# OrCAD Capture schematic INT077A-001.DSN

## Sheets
1 P1_8044: size C; title: TUSB8044RGCEVM INT077-001; rev: A.0; company: Texas Instruments, CIS/ICP; note: GAGGIA.DSN
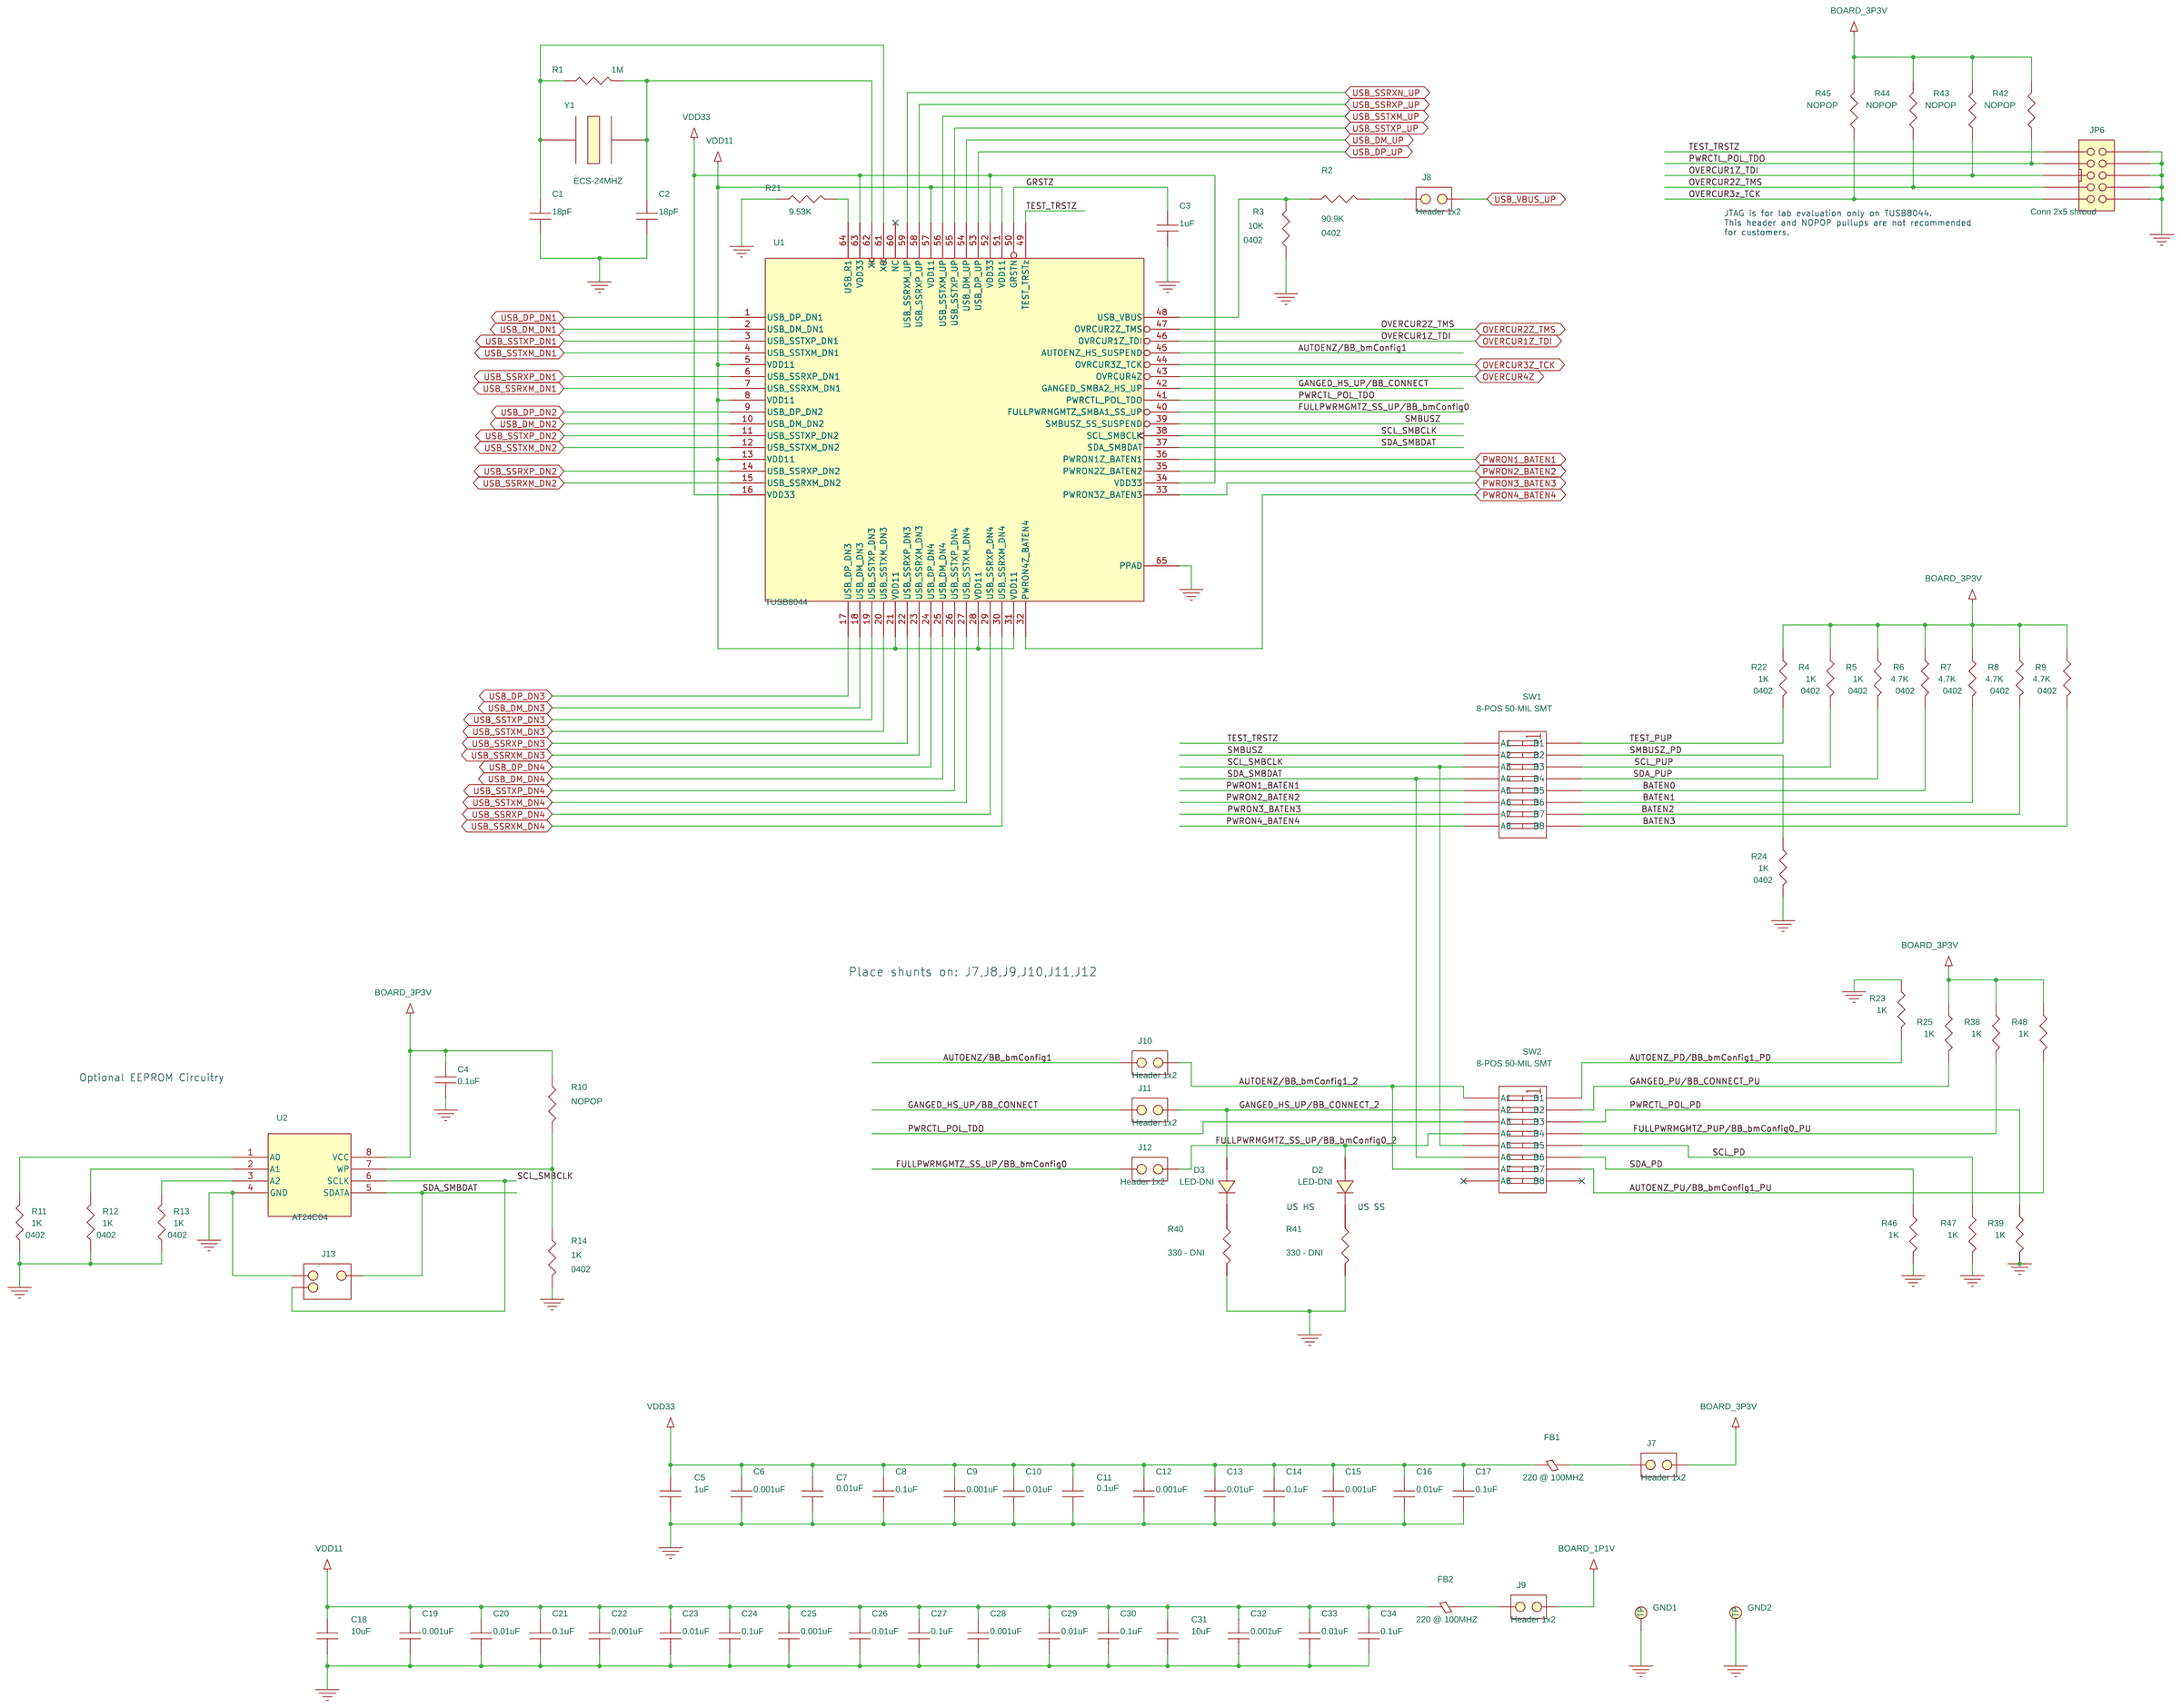
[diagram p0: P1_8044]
2 P2_CONNECTORS: size C; title: TUSB8044RGCEVM INT077-001: USB3 CONNECTORS
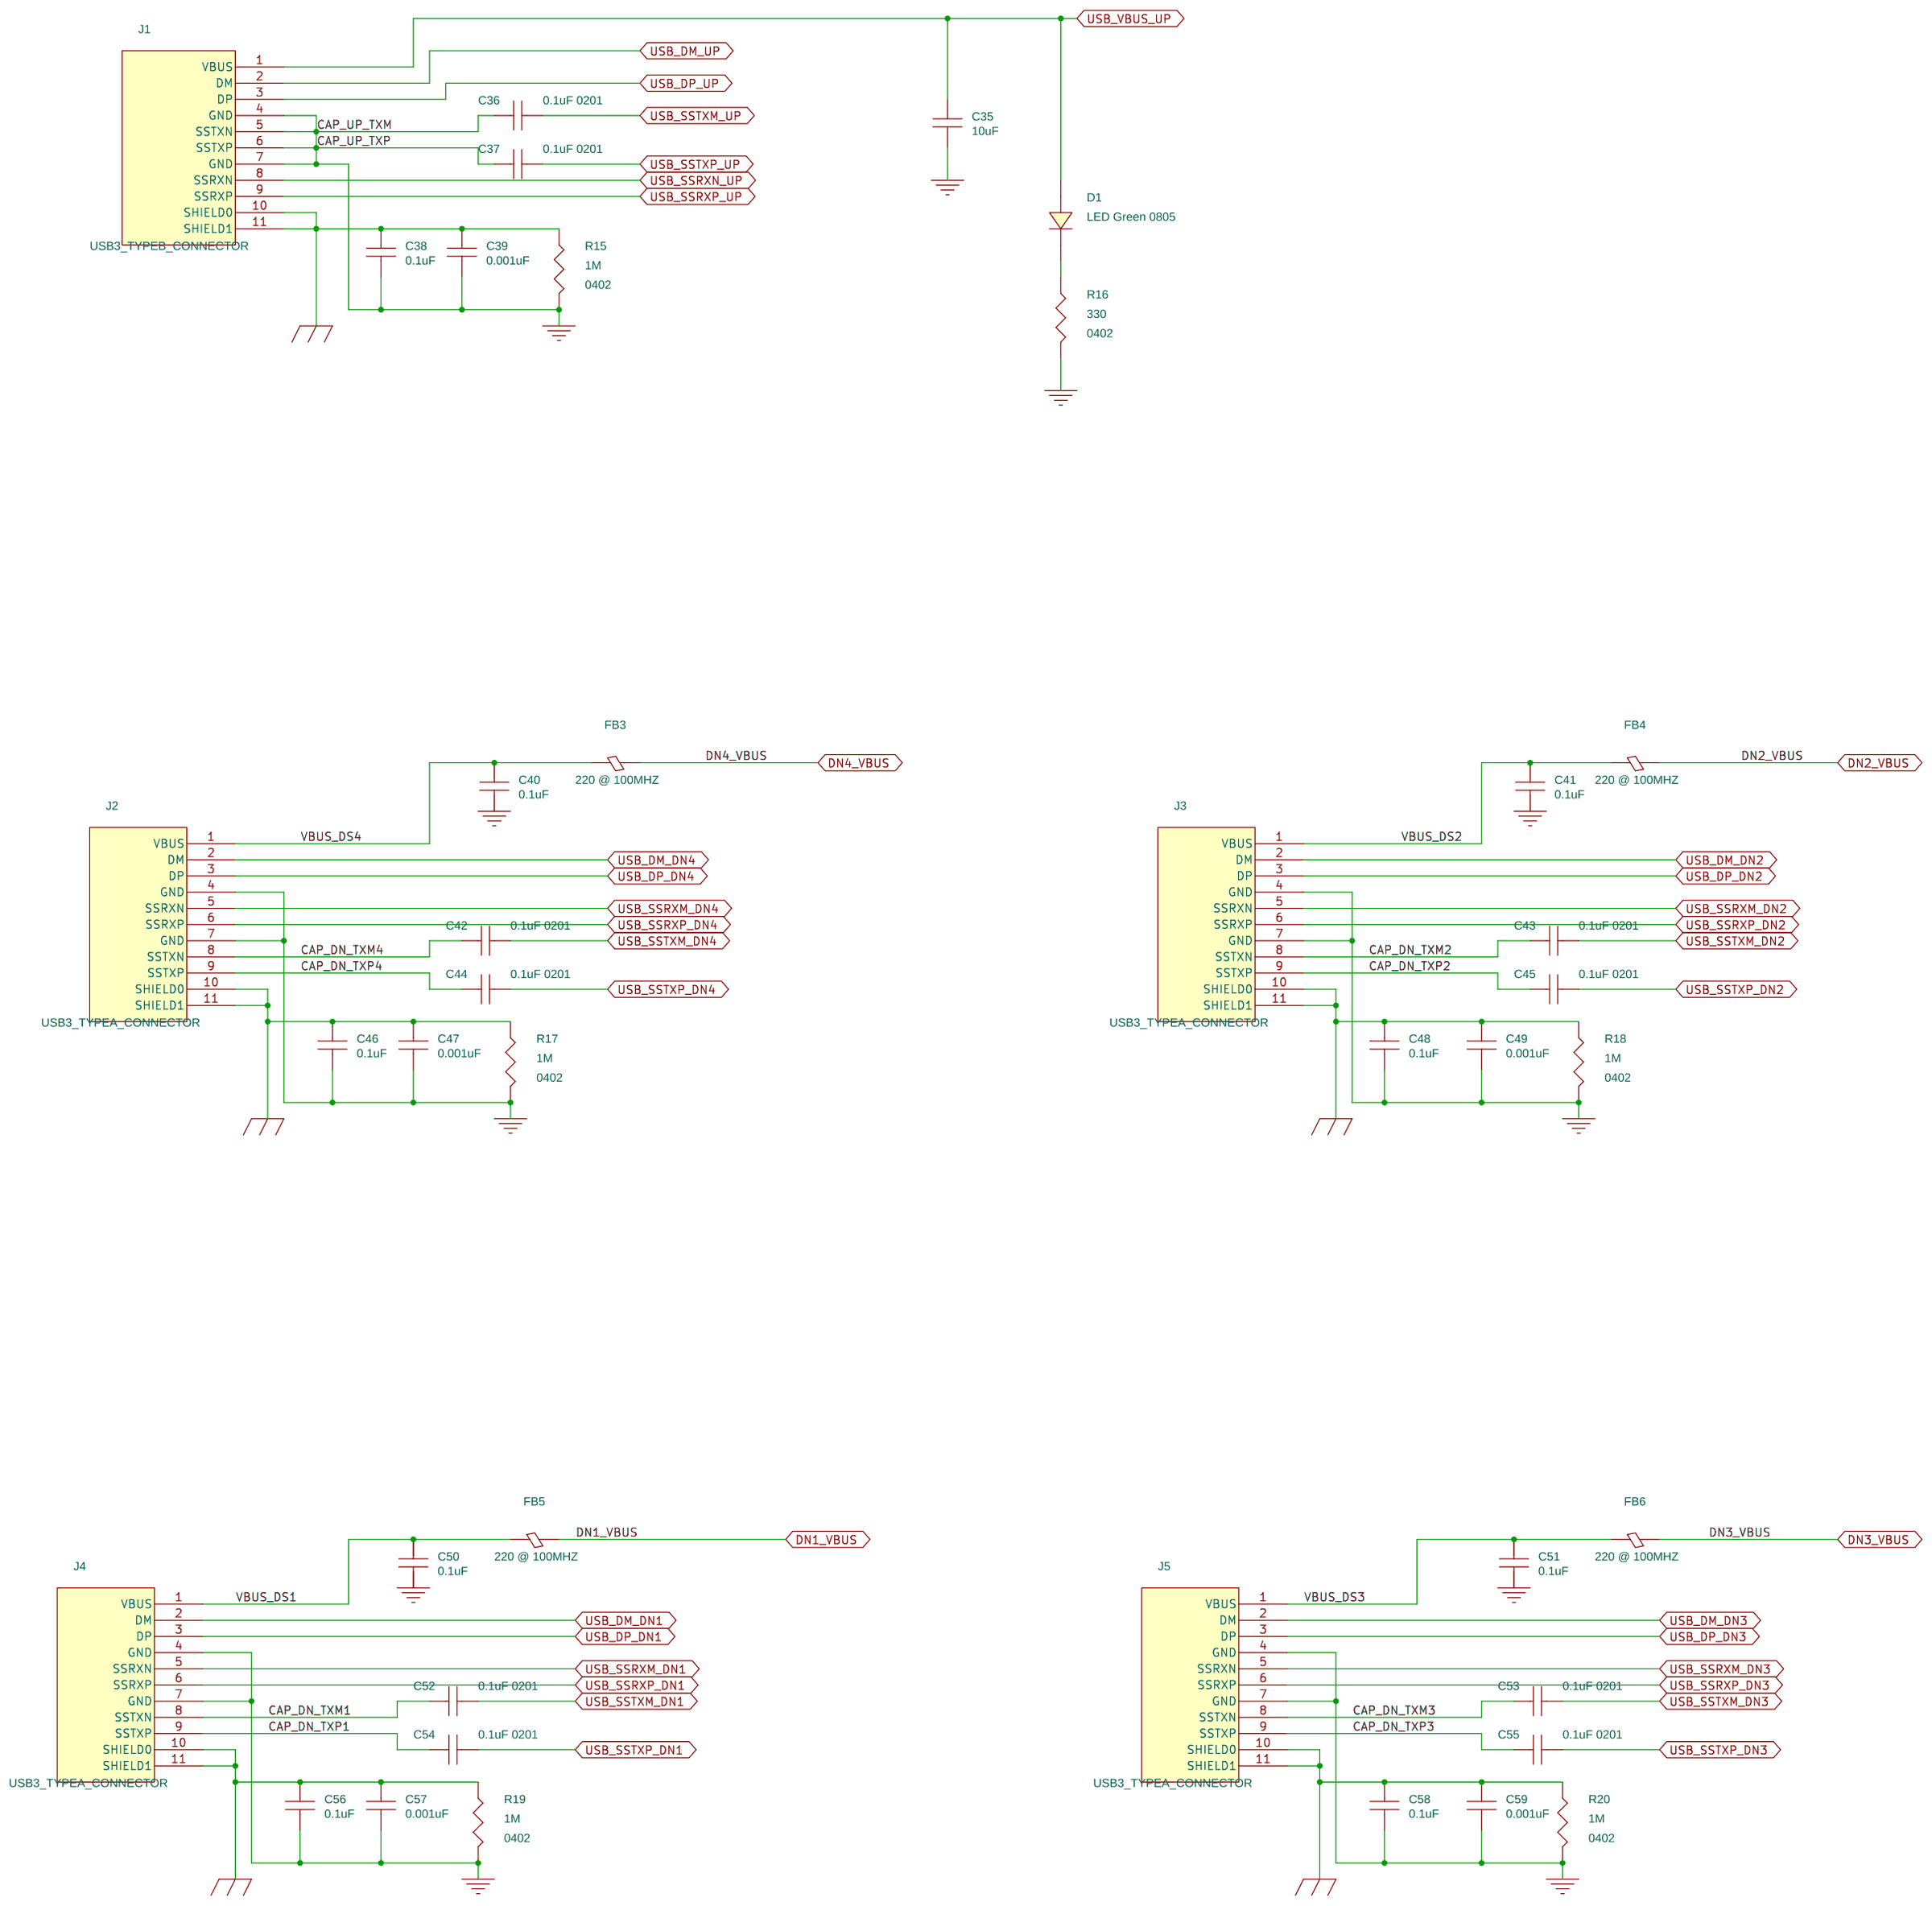
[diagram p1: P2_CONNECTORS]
3 P3_POWER: size C; title: TUSB8044RGCEVM INT077-001: POWER
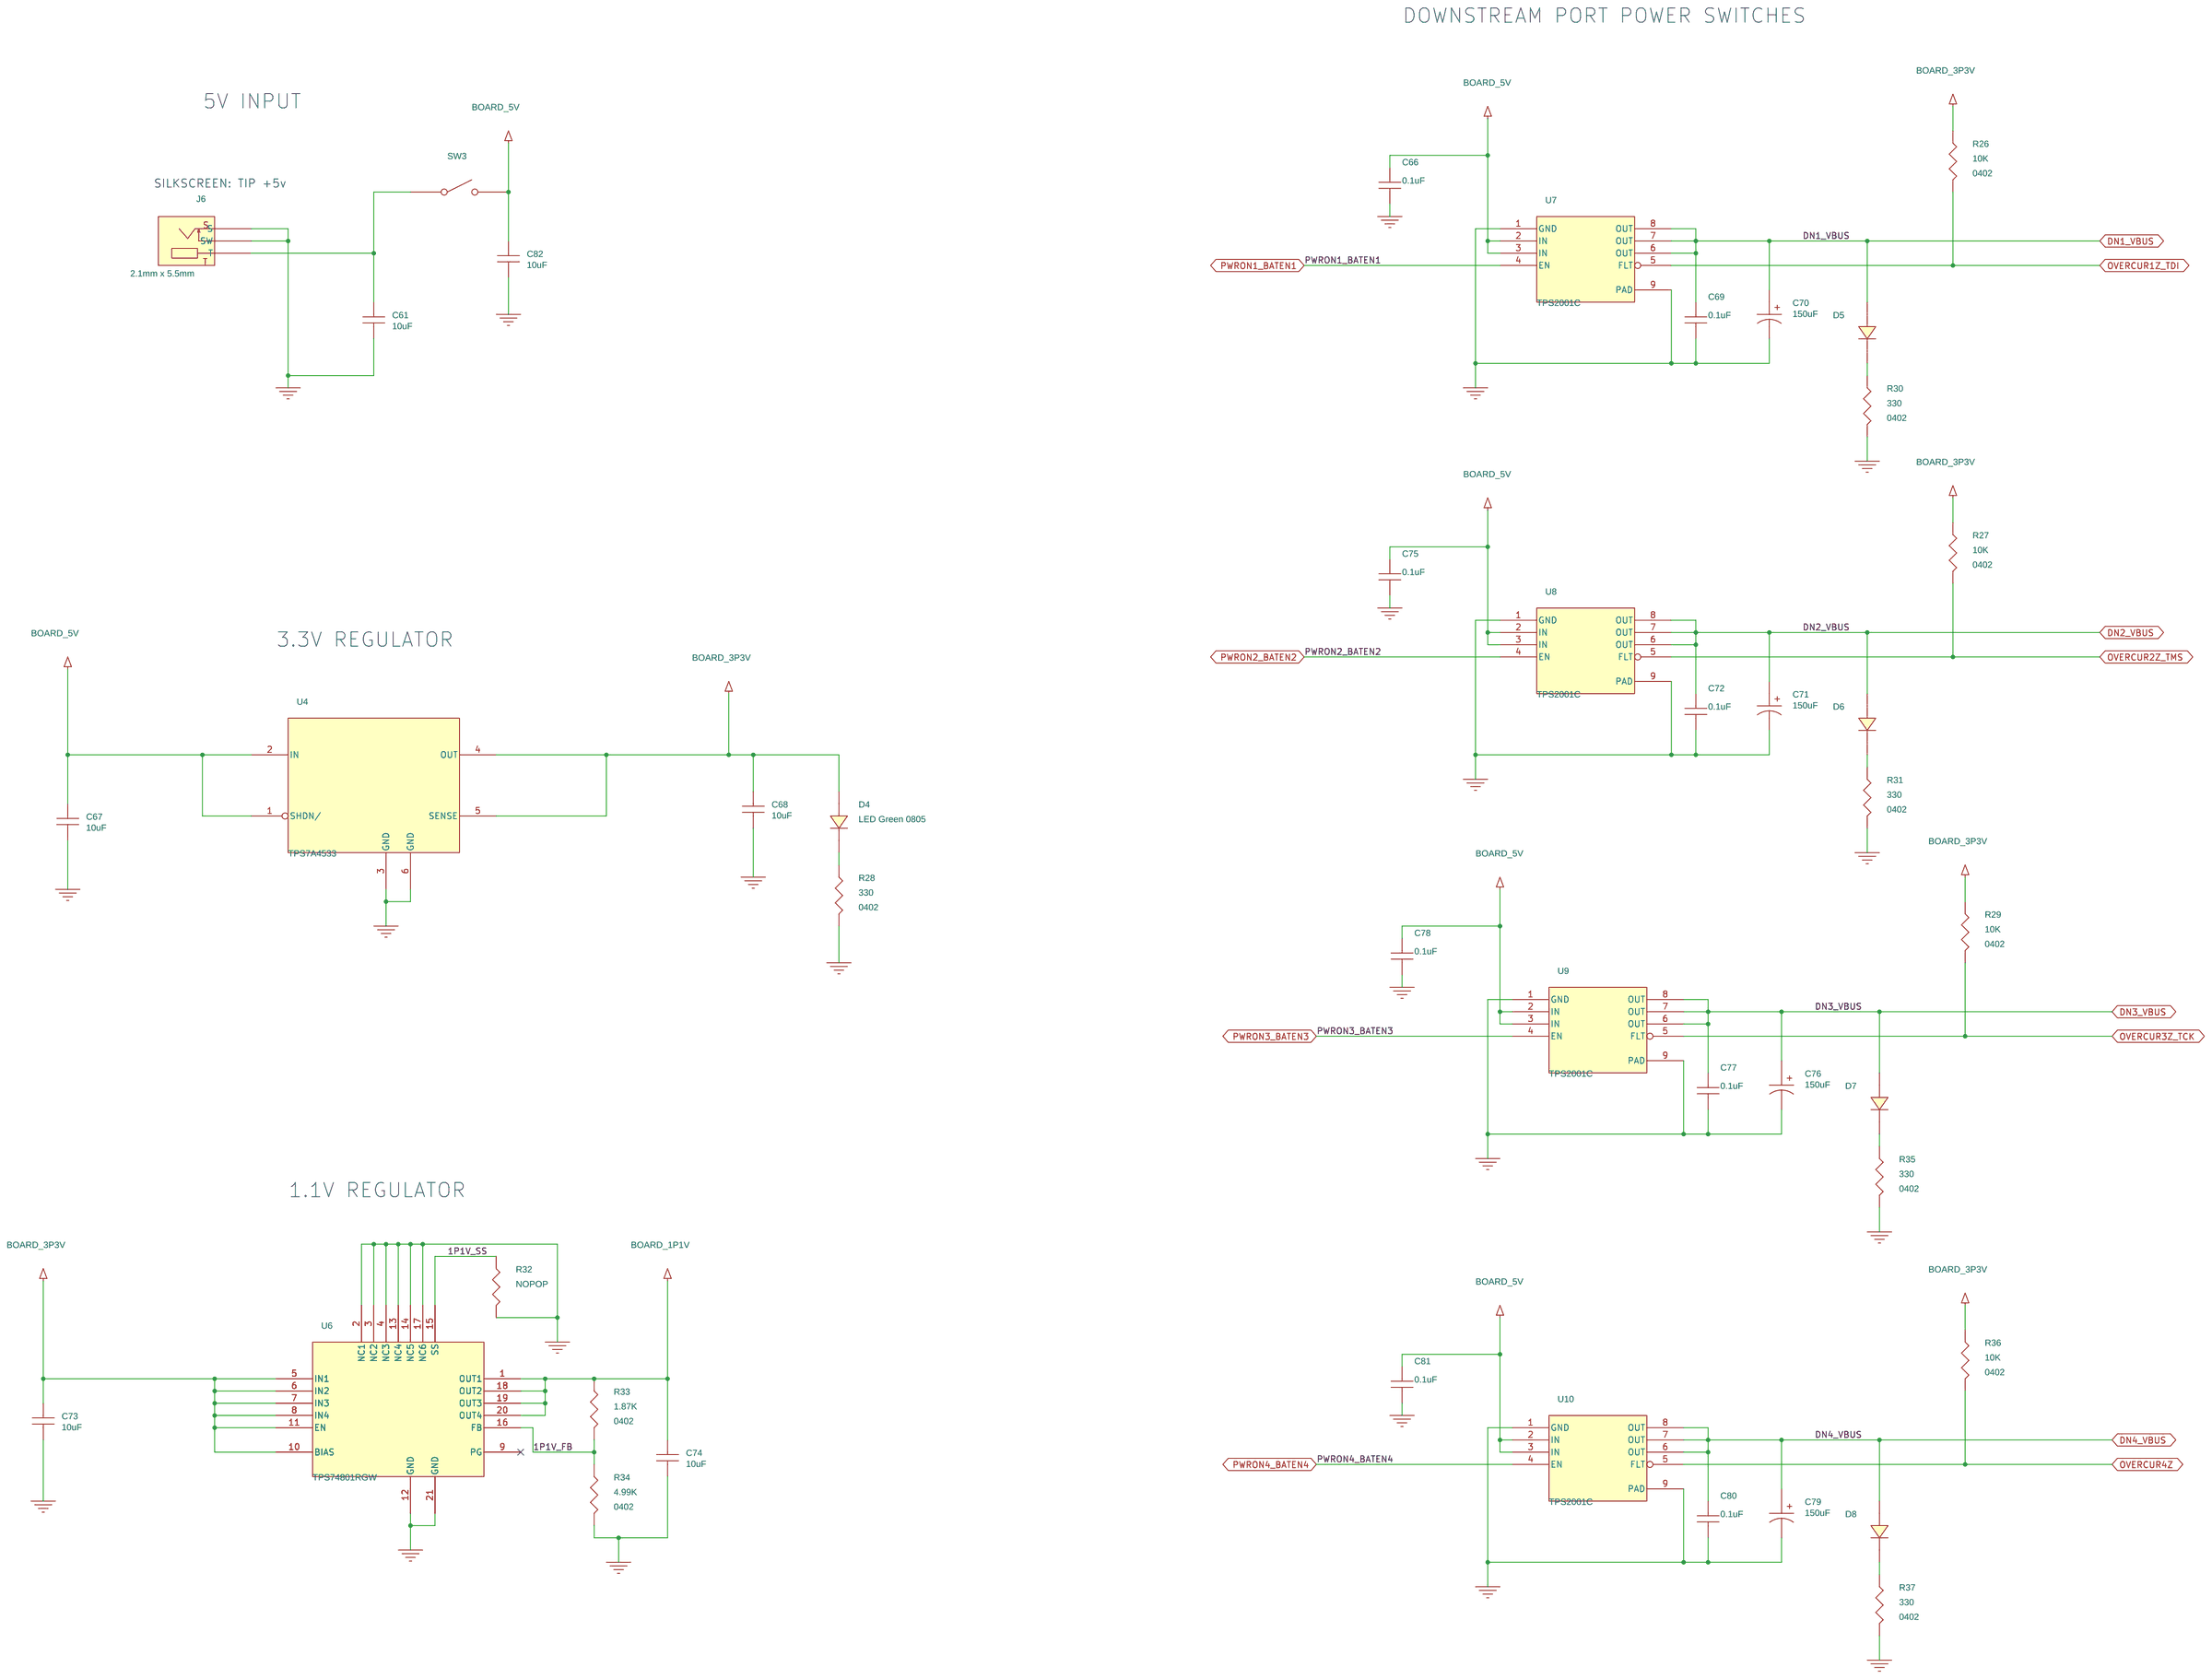
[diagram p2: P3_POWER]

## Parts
sheet P1_8044
C1  18pF  [0402]
C2  18pF  [0402]
C3  1uF  [0402]
C4  0.1uF  [0402]
C5  1uF  [0805]
C6  0.001uF  [0201]
C7  0.01uF  [0201]
C8  0.1uF  [0201]
C9  0.001uF  [0201]
C10  0.01uF  [0201]
C11  0.1uF  [0201]
C12  0.001uF  [0201]
C13  0.01uF  [0201]
C14  0.1uF  [0201]
C15  0.001uF  [0201]
C16  0.01uF  [0201]
C17  0.1uF  [0201]
C18  10uF  [1206]
C19  0.001uF  [0201]
C20  0.01uF  [0201]
C21  0.1uF  [0201]
C22  0.001uF  [0201]
C23  0.01uF  [0201]
C24  0.1uF  [0201]
C25  0.001uF  [0201]
C26  0.01uF  [0201]
C27  0.1uF  [0201]
C28  0.001uF  [0201]
C29  0.01uF  [0201]
C30  0.1uF  [0201]
C31  10uF  [1206]
C32  0.001uF  [0201]
C33  0.01uF  [0201]
C34  0.1uF  [0201]
D2  LED-DNI  [0805]
D3  LED-DNI  [0805]
FB1  220 @ 100MHZ  [0603]
FB2  220 @ 100MHZ  [0603]
GND1  TEST POINT  [testloop]
GND2  TEST POINT  [testloop]
J7  Header 1x2  [HDR_2X1]
J8  Header 1x2  [HDR_2X1]
J9  Header 1x2  [HDR_2X1]
J10  Header 1x2  [HDR_2X1]
J11  Header 1x2  [HDR_2X1]
J12  Header 1x2  [HDR_2X1]
J13  Header 1x2  [hdr_thvt_3pin_100]
JP6  Conn 2x5 shroud  [eprt-conn-00002-0001]
R1  1M  [0402]
R2  90.9K  [0402]
R3  10K  [0402]
R4  1K  [0402]
R5  1K  [0402]
R6  4.7K  [0402]
R7  4.7K  [0402]
R8  4.7K  [0402]
R9  4.7K  [0402]
R10  NOPOP  [0402]
R11  1K  [0402]
R12  1K  [0402]
R13  1K  [0402]
R14  1K  [0402]
R21  9.53K  [0402]
R22  1K  [0402]
R23  1K  [0402]
R24  1K  [0402]
R25  1K  [0402]
R38  1K  [0402]
R39  1K  [0402]
R40  330 - DNI  [0402]
R41  330 - DNI  [0402]
R42  NOPOP  [0402]
R43  NOPOP  [0402]
R44  NOPOP  [0402]
R45  NOPOP  [0402]
R46  1K  [0402]
R47  1K  [0402]
R48  1K  [0402]
SW1  8-POS 50-MIL SMT  [TDA08H0SK1]
SW2  8-POS 50-MIL SMT  [TDA08H0SK1]
U1  TUSB8044  [GEM050-0064BJ02]
U2  AT24C04  [dip8]
Y1  ECS-24MHZ  [ECX-53B]
sheet P2_CONNECTORS
C35  10uF  [1206]
C36  0.1uF 0201  [0201]
C37  0.1uF 0201  [0201]
C38  0.1uF  [0402]
C39  0.001uF  [0402]
C40  0.1uF  [0402]
C41  0.1uF  [0402]
C42  0.1uF 0201  [0201]
C43  0.1uF 0201  [0201]
C44  0.1uF 0201  [0201]
C45  0.1uF 0201  [0201]
C46  0.1uF  [0402]
C47  0.001uF  [0402]
C48  0.1uF  [0402]
C49  0.001uF  [0402]
C50  0.1uF  [0402]
C51  0.1uF  [0402]
C52  0.1uF 0201  [0201]
C53  0.1uF 0201  [0201]
C54  0.1uF 0201  [0201]
C55  0.1uF 0201  [0201]
C56  0.1uF  [0402]
C57  0.001uF  [0402]
C58  0.1uF  [0402]
C59  0.001uF  [0402]
D1  LED Green 0805  [0805]
FB3  220 @ 100MHZ  [0603]
FB4  220 @ 100MHZ  [0603]
FB5  220 @ 100MHZ  [0603]
FB6  220 @ 100MHZ  [0603]
J1  USB3_TYPEB_CONNECTOR  [USB3_TYPEB_AK4AA009]
J2  USB3_TYPEA_CONNECTOR  [USB3_TYPEA]
J3  USB3_TYPEA_CONNECTOR  [USB3_TYPEA]
J4  USB3_TYPEA_CONNECTOR  [USB3_TYPEA]
J5  USB3_TYPEA_CONNECTOR  [USB3_TYPEA]
R15  1M  [0402]
R16  330  [0402]
R17  1M  [0402]
R18  1M  [0402]
R19  1M  [0402]
R20  1M  [0402]
sheet P3_POWER
C61  10uF  [1206]
C66  0.1uF  [0402]
C67  10uF  [1206]
C68  10uF  [1206]
C69  0.1uF  [0402]
C70  150uF  [7343]
C71  150uF  [7343]
C72  0.1uF  [0402]
C73  10uF  [1206]
C74  10uF  [1206]
C75  0.1uF  [0402]
C76  150uF  [7343]
C77  0.1uF  [0402]
C78  0.1uF  [0402]
C79  150uF  [7343]
C80  0.1uF  [0402]
C81  0.1uF  [0402]
C82  10uF  [1206]
D4  LED Green 0805  [0805]
D5  LED Green 0805  [0805]
D6  LED Green 0805  [0805]
D7  LED Green 0805  [0805]
D8  LED Green 0805  [0805]
J6  2.1mm x 5.5mm  [PJ-202AH]
R26  10K  [0402]
R27  10K  [0402]
R28  330  [0402]
R29  10K  [0402]
R30  330  [0402]
R31  330  [0402]
R32  NOPOP  [0402]
R33  1.87K  [0402]
R34  4.99K  [0402]
R35  330  [0402]
R36  10K  [0402]
R37  330  [0402]
SW3  L101011MS02Q  [l101_switch]
U4  TPS7A4533  [KTT_6pin]
U6  TPS74801RGW  [RGW20]
U7  TPS2001C  [dgn8]
U8  TPS2001C  [dgn8]
U9  TPS2001C  [dgn8]
U10  TPS2001C  [dgn8]

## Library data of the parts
C1-C59 C61 C66-C69 C72-C75 C77 C78 C80-C82 = CAP_NP
D1-D8 = DIODE: Manuf: Lumex; Manuf PN: SML-LX0805GC-TR
FB1-FB6 = FERRITE_BEAD: Device: BEAD1806; MFC: MuRata; Manuf: MuRata; Manuf PN: BLM18EG221SN1D; Part Number: BLM18EG221SN1D; Part#: BLM18EG221SN1D
GND1 GND2 = Test_Point_Small
J7-J12 = HDR2X1_M_.1
J13 = HDR2X1_M__0.1
JP6 = eprt-conn-00002-0000: Manuf: 3M; Manuf PN: 2510-6003UB; Manufacturer: 3M; Manufacturer's Part#: 2510-6003UB; PART_NUMBER: DRY2JTAG_3P3; Part#: eprt-conn-00002-0002; TI_Silktext: DRY2JTAG_3P3
R1 R4-R20 R22-R48 = R: Tolerance: 5%
R2 R3 R21 = R: Tolerance: 1%
SW1 SW2 = SW_DIP-8_SM_0: Manuf: C&K(ITT-CANNON); Manuf PN: TDA08H0SK1R; Vendor: C&K (ITT-CANNON); Vendor Part Number: TDA08H0SK1R
U1 = TUSB8040_41: MFC: TEXAS INSTRUMENTS; MFC PN: TUSB8041
U2 = AT24C04
Y1 = ECS-25MHZ
J1 = USB3_TYPEB_CONNECTOR: Manuf: Foxconn; Manuf PN: UEB11123-2JK1-4H; PART_NUMBER: USB3_UP0; TI_Silktext: USB3_UP0
J2-J5 = USB3_TYPEA_CONNECTER: Manuf: Foxconn; Manuf PN: UEA11123-4HK1-4H; PART_NUMBER: USB3_DS2; TI_Silktext: USB3_DS2
C70 C71 C76 C79 = CAPACITOR_POL: Manuf: Kemet
J6 = BNC_2: MANUF: CUI STACK; PART_NUMBER: 5V_SUPPLY; TI_Silktext: 5V_SUPPLY
SW3 = SW_SPST
U4 = TPS79633KTT_2: Manuf PN: TPS79633KTT
U6 = TPS74801RGW_1
U7-U10 = TPS2560DRC_3

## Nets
GND: C1.2 C2.2 C3.2 C4.2 C5.2 C6.2 C7.2 C8.2 C9.2 C10.2 C11.2 C12.2 C13.2 C14.2 C15.2 C16.2 C17.2 C18.2 C19.2 C20.2 C21.2 C22.2 C23.2 C24.2 C25.2 C26.2 C27.2 C28.2 C29.2 C30.2 C31.2 C32.2 C33.2 C34.2 C35.2 C38.2 C39.2 C40.2 C41.2 C46.2 C47.2 C48.2 C49.2 C50.2 C51.2 C56.2 C57.2 C58.2 C59.2 C61.2 C66.2 C67.2 C68.2 C69.2 C70.2 C71.2 C72.2 C73.2 C74.2 C75.2 C76.2 C77.2 C78.2 C79.2 C80.2 C81.2 C82.2 GND1.1(TP) GND2.1(TP) J1.4(GND) J1.7(GND) J2.4(GND) J2.7(GND) J3.4(GND) J3.7(GND) J4.4(GND) J4.7(GND) J5.4(GND) J5.7(GND) J6.2(S) J6.3(SW) J13.2 JP6.2 JP6.4 JP6.6 JP6.8 JP6.10 R3.2 R11.1 R12.1 R13.1 R14.2 R15.2 R16.2 R17.2 R18.2 R19.2 R20.2 R21.1 R23.2 R24.1 R28.2 R30.2 R31.2 R32.2 R34.2 R35.2 R37.2 R39.1 R40.1 R41.1 R46.1 R47.1 U1.65(PPAD) U2.4(GND) U4.3(GND) U4.6(GND) U6.2(NC1) U6.3(NC2) U6.4(NC3) U6.12(GND) U6.13(NC4) U6.14(NC5) U6.17(NC6) U6.21(GND) U7.1(GND) U7.9(PAD) U8.1(GND) U8.9(PAD) U9.1(GND) U9.9(PAD) U10.1(GND) U10.9(PAD)
GND_EARTH: C38.1 C39.1 C46.1 C47.1 C48.1 C49.1 C56.1 C57.1 C58.1 C59.1 J1.10(SHIELD0) J1.11(SHIELD1) J2.10(SHIELD0) J2.11(SHIELD1) J3.10(SHIELD0) J3.11(SHIELD1) J4.10(SHIELD0) J4.11(SHIELD1) J5.10(SHIELD0) J5.11(SHIELD1) R15.1 R17.1 R18.1 R19.1 R20.1
VBUS_DS1: C50.1 FB5.1 J4.1(VBUS)
VBUS_DS2: C41.1 FB4.1 J3.1(VBUS)
VBUS_DS3: C51.1 FB6.1 J5.1(VBUS)
VBUS_DS4: C40.1 FB3.1 J2.1(VBUS)
VDD11: C18.1 C19.1 C20.1 C21.1 C22.1 C23.1 C24.1 C25.1 C26.1 C27.1 C28.1 C29.1 C30.1 C31.1 C32.1 C33.1 C34.1 FB2.1 U1.5(VDD11) U1.8(VDD11) U1.13(VDD11) U1.21(VDD11) U1.28(VDD11) U1.31(VDD11) U1.51(VDD11) U1.57(VDD11)
VDD33: C5.1 C6.1 C7.1 C8.1 C9.1 C10.1 C11.1 C12.1 C13.1 C14.1 C15.1 C16.1 C17.1 FB1.1 U1.16(VDD33) U1.34(VDD33) U1.52(VDD33) U1.63(VDD33)
1P1V_FB: R33.2 R34.1 U6.16(FB)
1P1V_SS: R32.1 U6.15(SS)
AUTOENZ/BB_bmConfig1: J10.1 U1.45(AUTOENZ_HS_SUSPEND)
AUTOENZ/BB_bmConfig1_2: J10.2 SW2.1(A1) SW2.7(A7)
AUTOENZ_PD/BB_bmConfig1_PD : R23.1 SW2.16(B1)
AUTOENZ_PU/BB_bmConfig1_PU: R48.1 SW2.10(B7)
BATEN0: R6.1 SW1.12(B5)
BATEN1: R7.1 SW1.11(B6)
BATEN2: R8.1 SW1.10(B7)
BATEN3: R9.1 SW1.9(B8)
BOARD_1P1V: C74.1 J9.2 R33.1 U6.1(OUT1) U6.18(OUT2) U6.19(OUT3) U6.20(OUT4)
BOARD_3P3V: C4.1 C68.1 C73.1 D4.1(A) J7.2 R4.2 R5.2 R6.2 R7.2 R8.2 R9.2 R10.1 R22.2 R25.2 R26.1 R27.1 R29.1 R36.1 R38.2 R42.1 R43.1 R44.1 R45.1 R48.2 U2.8(VCC) U4.4(OUT) U4.5(SENSE) U6.5(IN1) U6.6(IN2) U6.7(IN3) U6.8(IN4) U6.10(BIAS) U6.11(EN)
BOARD_5V: C66.1 C67.1 C75.1 C78.1 C81.1 C82.1 SW3.2 U4.1(SHDN/) U4.2(IN) U7.2(IN) U7.3(IN) U8.2(IN) U8.3(IN) U9.2(IN) U9.3(IN) U10.2(IN) U10.3(IN)
CAP_DN_TXM1: C52.1 J4.8(SSTXN)
CAP_DN_TXM2: C43.1 J3.8(SSTXN)
CAP_DN_TXM3: C53.1 J5.8(SSTXN)
CAP_DN_TXM4: C42.1 J2.8(SSTXN)
CAP_DN_TXP1: C54.1 J4.9(SSTXP)
CAP_DN_TXP2: C45.1 J3.9(SSTXP)
CAP_DN_TXP3: C55.1 J5.9(SSTXP)
CAP_DN_TXP4: C44.1 J2.9(SSTXP)
CAP_UP_TXM: C36.1 J1.5(SSTXN)
CAP_UP_TXP: C37.1 J1.6(SSTXP)
DN1_VBUS: C69.1 C70.1 D5.1(A) FB5.2 U7.6(OUT) U7.7(OUT) U7.8(OUT)
DN2_VBUS: C71.1 C72.1 D6.1(A) FB4.2 U8.6(OUT) U8.7(OUT) U8.8(OUT)
DN3_VBUS: C76.1 C77.1 D7.1(A) FB6.2 U9.6(OUT) U9.7(OUT) U9.8(OUT)
DN4_VBUS: C79.1 C80.1 D8.1(A) FB3.2 U10.6(OUT) U10.7(OUT) U10.8(OUT)
FULLPWRMGMTZ_PUP/BB_bmConfig0_PU: R38.1 SW2.13(B4)
FULLPWRMGMTZ_SS_UP/BB_bmConfig0: J12.1 U1.40(FULLPWRMGMTZ_SMBA1_SS_UP)
FULLPWRMGMTZ_SS_UP/BB_bmConfig0_2: D2.1(A) J12.2 SW2.4(A4)
GANGED_HS_UP/BB_CONNECT: J11.1 U1.42(GANGED_SMBA2_HS_UP)
GANGED_HS_UP/BB_CONNECT_2: D3.1(A) J11.2 SW2.2(A2)
GANGED_PU/BB_CONNECT_PU: R25.1 SW2.15(B2)
GRSTZ: C3.1 U1.50(GRSTN)
OVERCUR1Z_TDI: JP6.5 R26.2 R43.2 U1.46(OVRCUR1Z_TDI) U7.5(FLT)
OVERCUR2Z_TMS: JP6.7 R27.2 R44.2 U1.47(OVRCUR2Z_TMS) U8.5(FLT)
OVERCUR3Z_TCK: JP6.9 R29.2 R45.2 U1.44(OVRCUR3Z_TCK) U9.5(FLT)
OVERCUR4Z: R36.2 U1.43(OVRCUR4Z) U10.5(FLT)
PWRCTL_POL_PD: R39.2 SW2.14(B3)
PWRCTL_POL_TDO: JP6.3 R42.2 SW2.3(A3) U1.41(PWRCTL_POL_TDO)
PWRON1_BATEN1: SW1.5(A5) U1.36(PWRON1Z_BATEN1) U7.4(EN)
PWRON2_BATEN2: SW1.6(A6) U1.35(PWRON2Z_BATEN2) U8.4(EN)
PWRON3_BATEN3: SW1.7(A7) U1.33(PWRON3Z_BATEN3) U9.4(EN)
PWRON4_BATEN4: SW1.8(A8) U1.32(PWRON4Z_BATEN4) U10.4(EN)
SCL_PD: R47.2 SW2.12(B5)
SCL_PUP: R4.1 SW1.14(B3)
SCL_SMBCLK: J13.1 SW1.3(A3) SW2.5(A5) U1.38(SCL_SMBCLK) U2.6(SCLK)
SDA_PD: R46.2 SW2.11(B6)
SDA_PUP: R5.1 SW1.13(B4)
SDA_SMBDAT: J13.3 SW1.4(A4) SW2.6(A6) U1.37(SDA_SMBDAT) U2.5(SDATA)
SMBUSZ: SW1.2(A2) U1.39(SMBUSZ_SS_SUSPEND)
SMBUSZ_PD: R24.2 SW1.15(B2)
TEST_PUP: R22.1 SW1.16(B1)
TEST_TRSTZ: JP6.1 SW1.1(A1) U1.49(TEST_TRSTz)
USB_DM_DN1: J4.2(DM) U1.2(USB_DM_DN1)
USB_DM_DN2: J3.2(DM) U1.10(USB_DM_DN2)
USB_DM_DN3: J5.2(DM) U1.18(USB_DM_DN3)
USB_DM_DN4: J2.2(DM) U1.25(USB_DM_DN4)
USB_DM_UP: J1.2(DM) U1.54(USB_DM_UP)
USB_DP_DN1: J4.3(DP) U1.1(USB_DP_DN1)
USB_DP_DN2: J3.3(DP) U1.9(USB_DP_DN2)
USB_DP_DN3: J5.3(DP) U1.17(USB_DP_DN3)
USB_DP_DN4: J2.3(DP) U1.24(USB_DP_DN4)
USB_DP_UP: J1.3(DP) U1.53(USB_DP_UP)
USB_SSRXM_DN1: J4.5(SSRXN) U1.7(USB_SSRXM_DN1)
USB_SSRXM_DN2: J3.5(SSRXN) U1.15(USB_SSRXM_DN2)
USB_SSRXM_DN3: J5.5(SSRXN) U1.23(USB_SSRXM_DN3)
USB_SSRXM_DN4: J2.5(SSRXN) U1.30(USB_SSRXM_DN4)
USB_SSRXN_UP: J1.8(SSRXN) U1.59(USB_SSRXM_UP)
USB_SSRXP_DN1: J4.6(SSRXP) U1.6(USB_SSRXP_DN1)
USB_SSRXP_DN2: J3.6(SSRXP) U1.14(USB_SSRXP_DN2)
USB_SSRXP_DN3: J5.6(SSRXP) U1.22(USB_SSRXP_DN3)
USB_SSRXP_DN4: J2.6(SSRXP) U1.29(USB_SSRXP_DN4)
USB_SSRXP_UP: J1.9(SSRXP) U1.58(USB_SSRXP_UP)
USB_SSTXM_DN1: C52.2 U1.4(USB_SSTXM_DN1)
USB_SSTXM_DN2: C43.2 U1.12(USB_SSTXM_DN2)
USB_SSTXM_DN3: C53.2 U1.20(USB_SSTXM_DN3)
USB_SSTXM_DN4: C42.2 U1.27(USB_SSTXM_DN4)
USB_SSTXM_UP: C36.2 U1.56(USB_SSTXM_UP)
USB_SSTXP_DN1: C54.2 U1.3(USB_SSTXP_DN1)
USB_SSTXP_DN2: C45.2 U1.11(USB_SSTXP_DN2)
USB_SSTXP_DN3: C55.2 U1.19(USB_SSTXP_DN3)
USB_SSTXP_DN4: C44.2 U1.26(USB_SSTXP_DN4)
USB_SSTXP_UP: C37.2 U1.55(USB_SSTXP_UP)
USB_VBUS_UP: C35.1 D1.1(A) J1.1(VBUS) J8.2
N17052812: R2.1 R3.1 U1.48(USB_VBUS)
N17181221: R10.2 R14.1 U2.7(WP)
N17181233: R11.2 U2.1(A0)
N17181243: R12.2 U2.2(A1)
N17181324: R13.2 U2.3(A2)
N17381185: D5.2(K) R30.1
N17383170: D1.2(K) R16.1
N17408350: D4.2(K) R28.1
N18334081: C2.1 R1.2 U1.62(XI) Y1.3(a3)
N18334093: C1.1 R1.1 U1.61(XO) Y1.1(a1)
N18711690: D6.2(K) R31.1
N18712170: D7.2(K) R35.1
N18712674: D8.2(K) R37.1
N18713919: R21.2 U1.64(USB_R1)
N18725733: J8.1 R2.2
N18726136: FB1.2 J7.1
N18726182: FB2.2 J9.1
N18744223: C61.1 J6.1(T) SW3.1
N18831450: D2.2(K) R41.2
N18831451: D3.2(K) R40.2

Not connected (* = marked no-connect by the designer): SW2 8(A8)* 9(B8)*; U1 60(NC)*; U6 9(PG)*; Y1 2(a2) 4(a4)

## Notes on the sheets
sheet 1
- JTAG is for lab evaluation only on TUSB8044.
  This header and NOPOP pullups are not recommended
  for customers.
- Place shunts on: J7,J8,J9,J10,J11,J12
- Optional EEPROM Circuitry
- US HS
- US SS
sheet 3
- DOWNSTREAM PORT POWER SWITCHES
- 5V INPUT
- SILKSCREEN: TIP +5v
- 3.3V REGULATOR
- 1.1V REGULATOR
